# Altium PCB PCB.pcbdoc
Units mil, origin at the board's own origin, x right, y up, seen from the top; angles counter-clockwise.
Board outline 3022 x 1802.5 mil, 4 copper layers (Top Layer, Inner1, Inner2, Bottom Layer); 70 components, 53 nets, 302 pads, 146 vias.
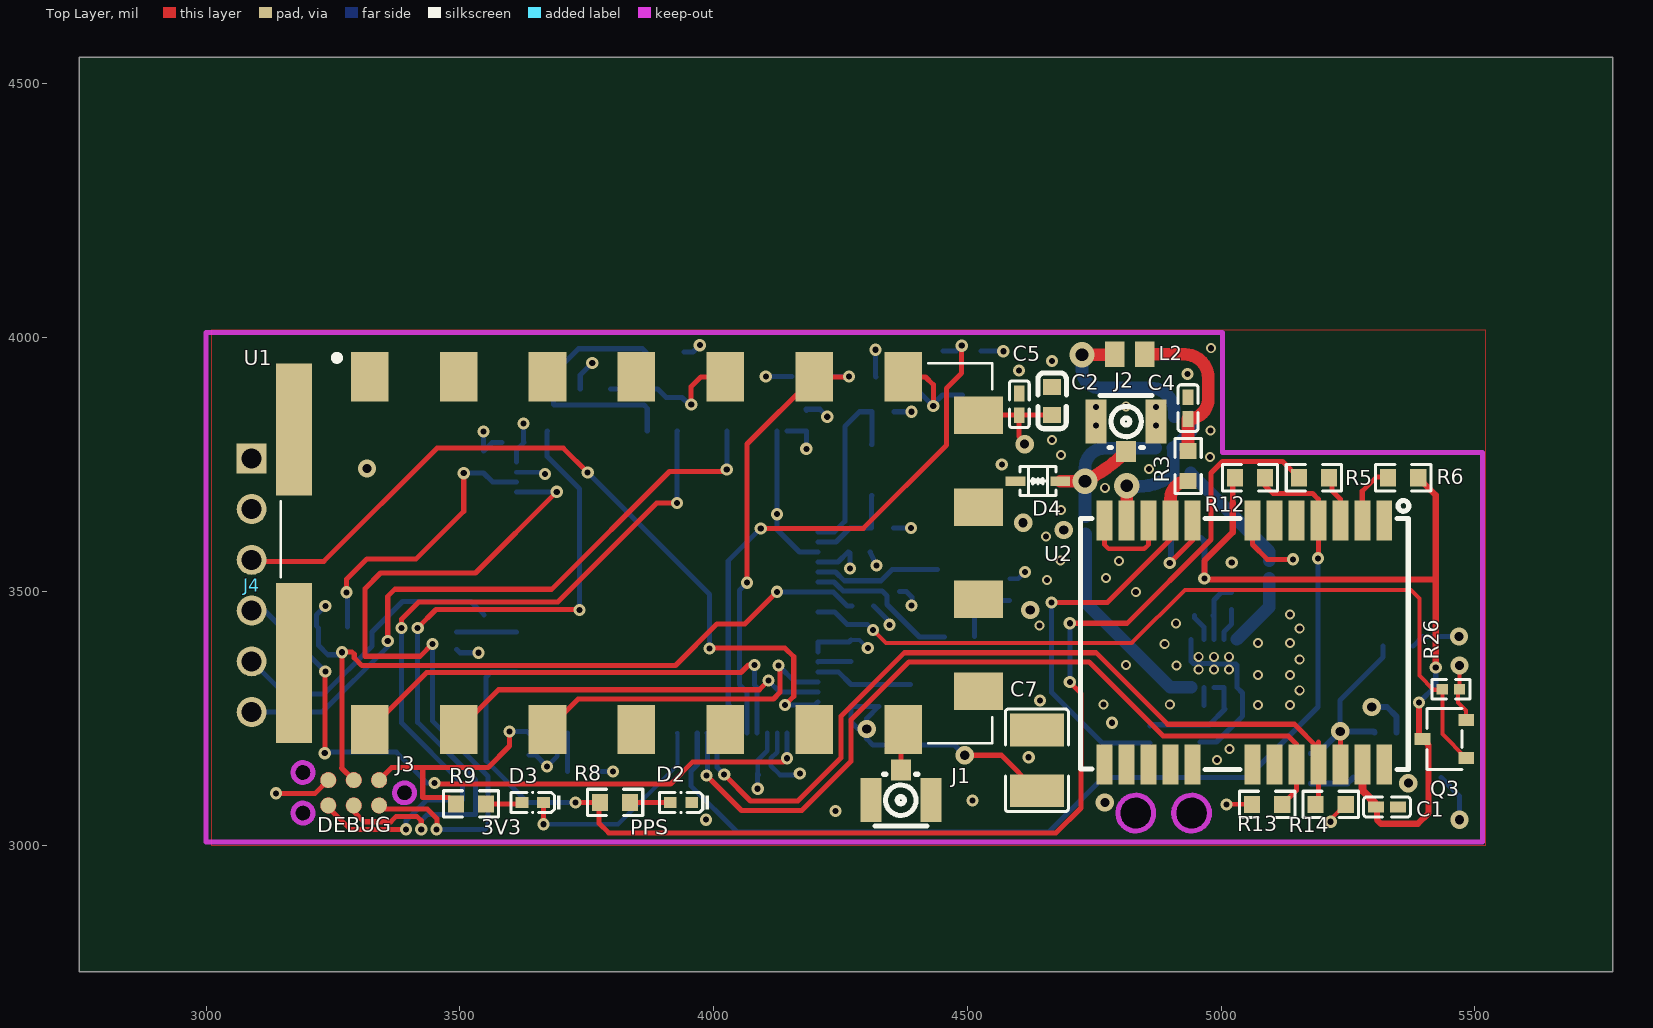
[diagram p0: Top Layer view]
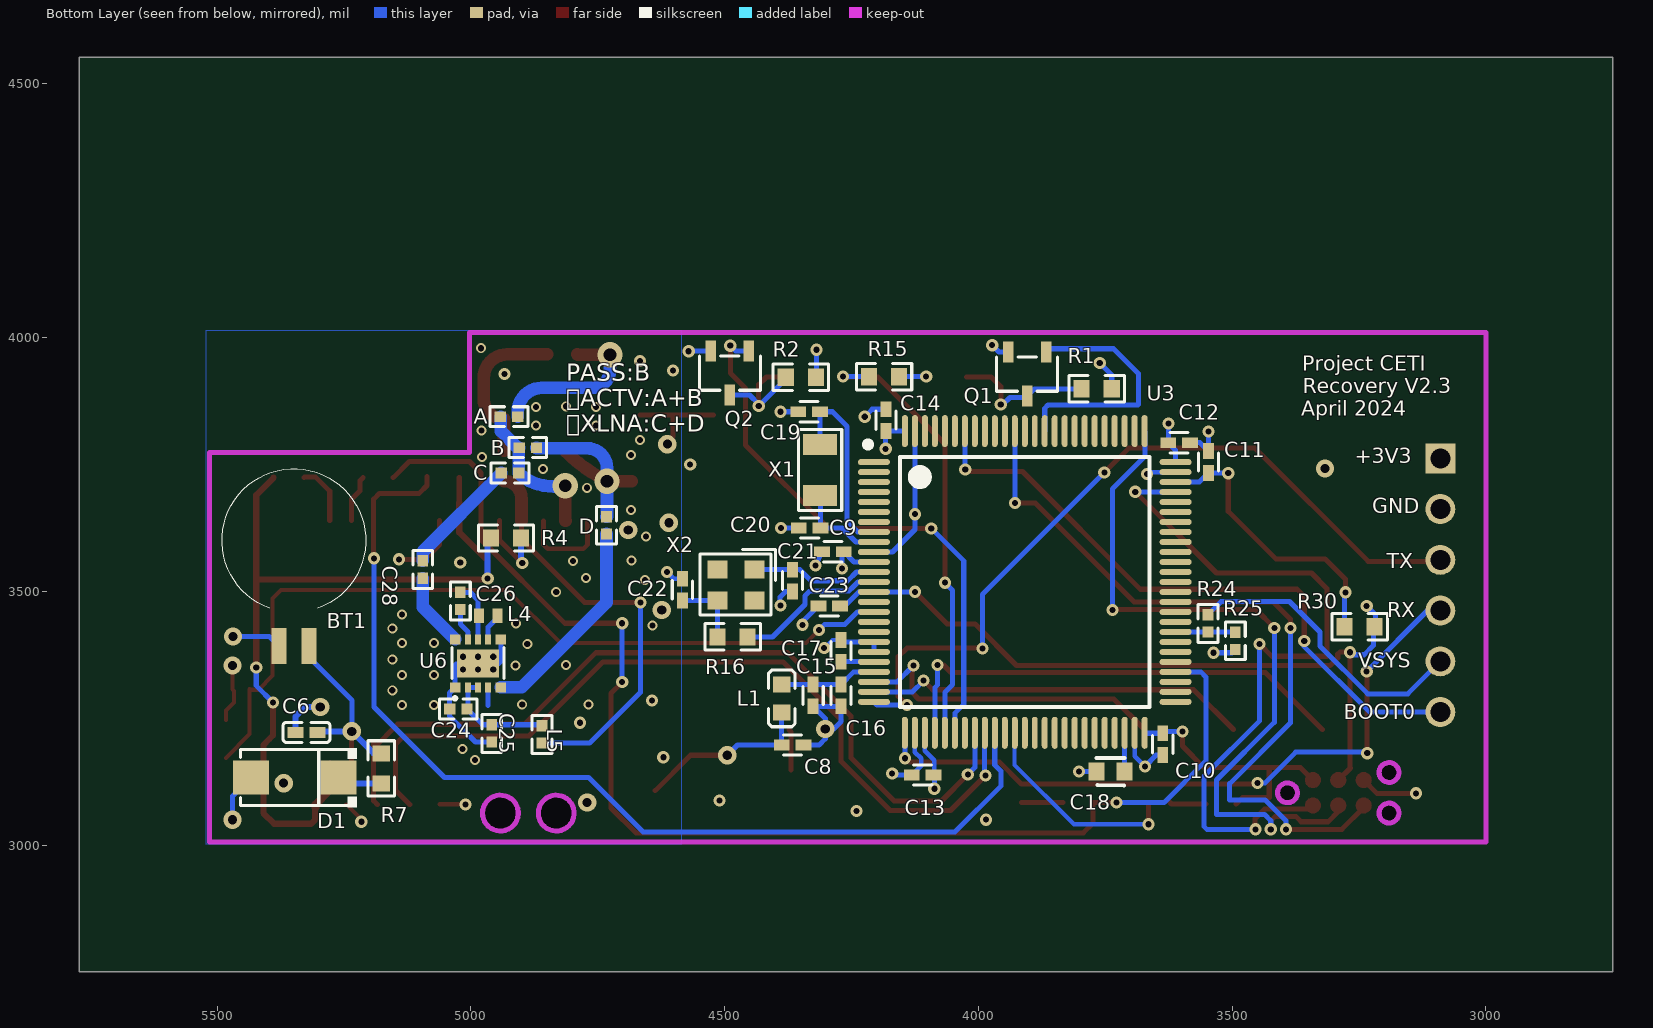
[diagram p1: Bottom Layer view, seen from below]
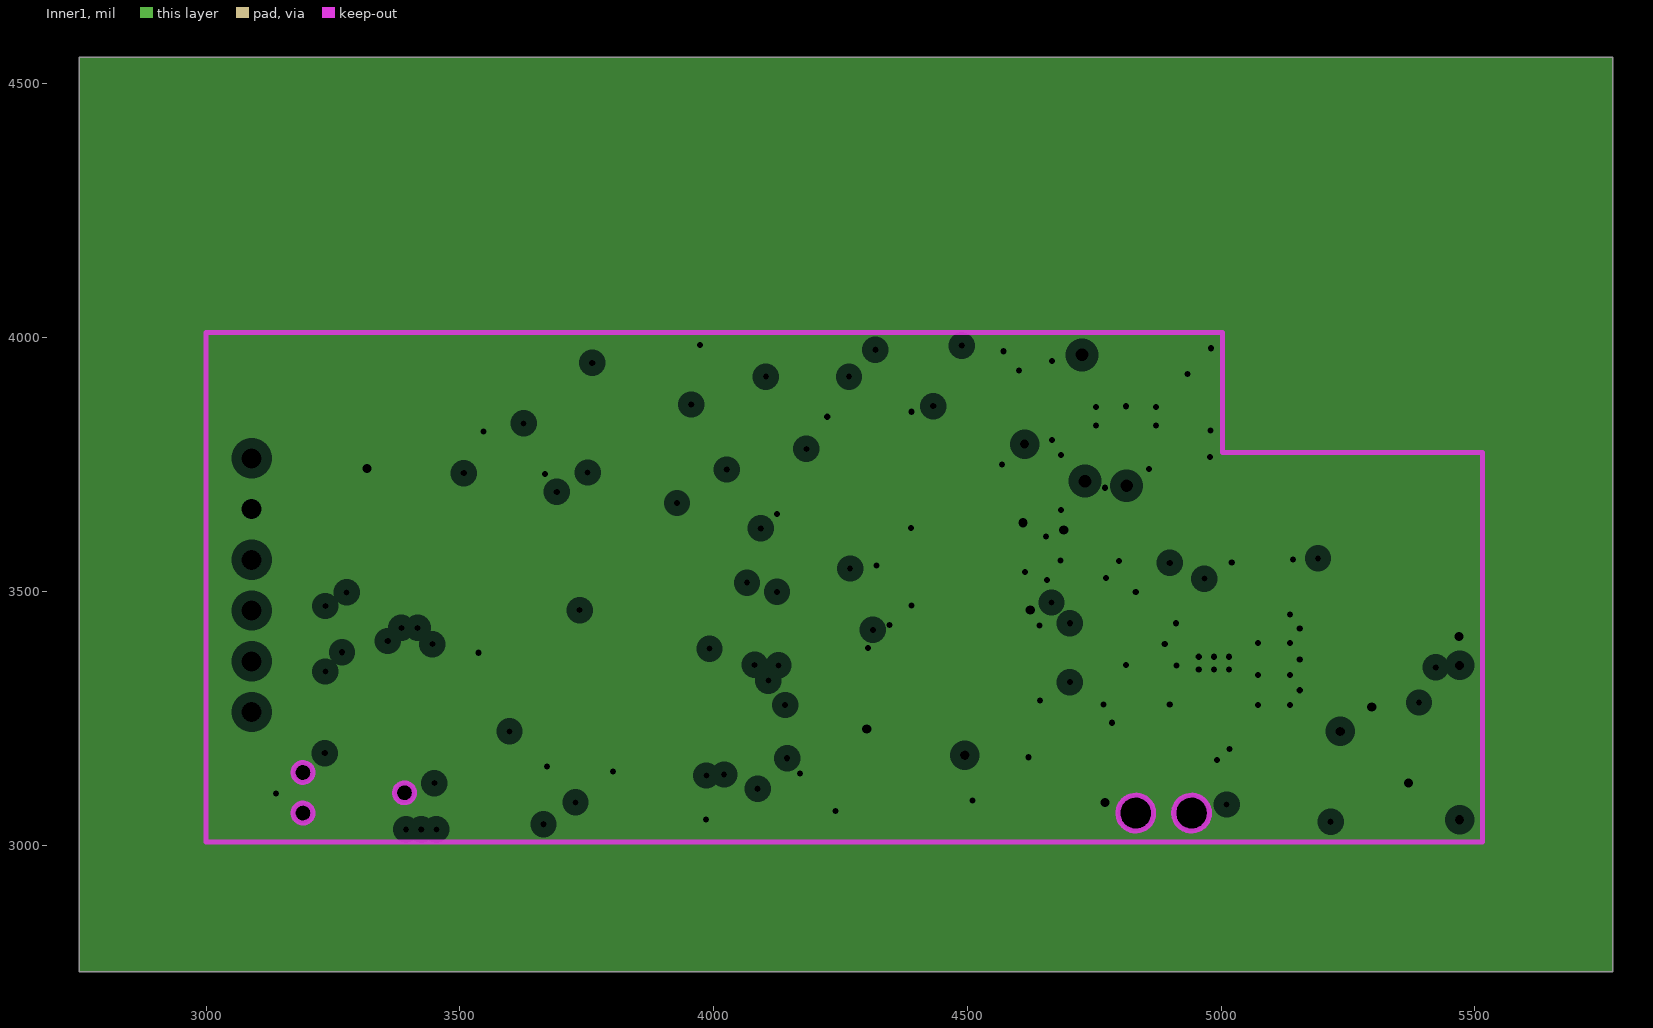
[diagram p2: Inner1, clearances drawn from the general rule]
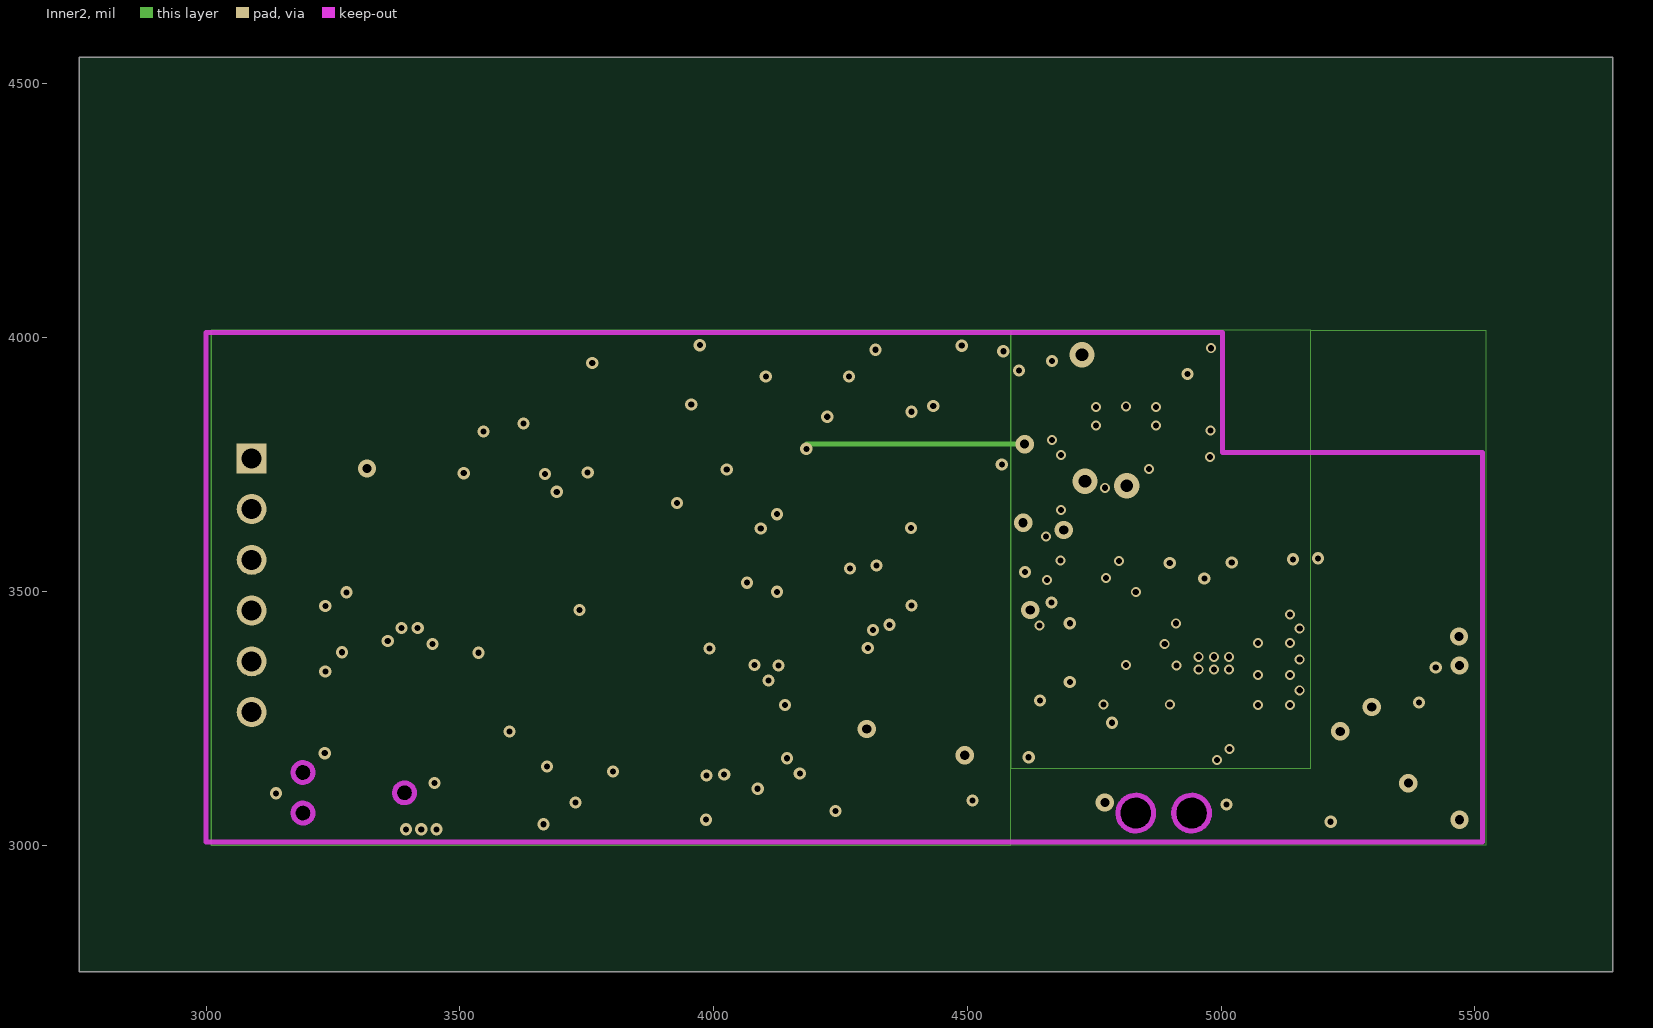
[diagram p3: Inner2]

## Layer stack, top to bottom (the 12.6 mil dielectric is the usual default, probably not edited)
Top Layer: signal copper (thickness not stored)
Dielectric: dielectric 12.6, FR-4, Dk 4.8
Inner1: plane copper (thickness not stored)
Dielectric: dielectric 12.6, FR-4, Dk 4.8
Inner2: signal copper (thickness not stored)
Dielectric: dielectric 12.6, FR-4, Dk 4.8
Bottom Layer: signal copper (thickness not stored)

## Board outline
5772,2750 2750,2750 2750,4552.5 5772,4552.5
cut-out: 4867.3,3063 ccw(c4832,3063) 4796.7,3063 ccw(c4832,3063)
cut-out: 4977.3,3063 ccw(c4942,3063) 4906.7,3063 ccw(c4942,3063)

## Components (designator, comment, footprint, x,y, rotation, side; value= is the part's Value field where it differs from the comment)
A "ERJ2GE0R00X" R0402 4925,3844 r0 bottom
B "ERJ2GE0R00X" R0402 4888,3783 r0 bottom
BT1 "MS621FE-FL11E" MS621FE-FL11E 5349,3392 r180 bottom
C "ERJ2GE0R00X" R0402 4923,3733 r180 bottom
C1 "CC0402KRX5R7BB105" C0402 5327,3075 r180 top
C2 "10uF" C0603 4667,3875 r270 top
C4 "GCM155R71C104KA55J" C0402 4935,3861 r270 top
C5 "100nF" C0402 4602.46,3868.46 r270 top
C6 "1uF" C0402 5324,3222 r180 bottom
C7 "100uF" C1210 4637,3167 r90 top
C8 "100nF" C0402 4366.33,3197.25 r0 bottom
C9 "100nF" C0402 4286.79,3577.79 r180 bottom
C10 "100nF" C0402 3636.79,3198.79 r90 bottom
C11 "100nF" C0402 3546.79,3754.79 r270 bottom
C12 "100nF" C0402 3604.79,3792.79 r0 bottom
C13 "100nF" C0402 4110,3138 r180 bottom
C14 "100nF" C0402 4182.33,3837.25 r270 bottom
C15 "1uF" C0402 4325.79,3294.79 r90 bottom
C16 "10nF" C0402 4270.79,3294.79 r90 bottom
C17 "100nF" C0402 4270.79,3382.79 r270 bottom
C18 "4.7uF" C0603 3739.79,3144.79 r180 bottom
C19 "15pF" C0402 4333.79,3853.79 r180 bottom
C20 "15pF" C0402 4332.79,3624.79 r180 bottom
C21 "6pF" C0402 4366.38,3521.2 r90 bottom
C22 "6pF" C0402 4583.38,3503.2 r270 bottom
C23 "100nF" C0402 4294,3471 r180 bottom
C24 "ERJ2GE0R00X" R0402 5025,3268 r180 bottom
C25 "ERJ2GE0R00X" R0402 4959,3220 r90 bottom
C26 "ERJ2GE0R00X" R0402 5021,3481 r90 bottom
C28 "ERJ2GE0R00X" R0402 5095,3543 r90 bottom
D "ERJ2GE0R00X" R0402 4733,3630 r270 bottom
D1 "SS14L" SMA_L4.4-W2.6-LS5.0-RD 5347,3133 r0 bottom
D2 "16-213/BHC-ZL1M2B6Y/3T" LED0402-RD_BLUE 3936,3084 r180 top
D3 "16-213/SDRC/S530-A3/TR8" LED0402-RD 3643.71,3084 r180 top
D4 "NI" SOD-323_L1.8-W1.3-LS2.5-BI 4639,3717 r0 top
J1 "1909763-1" ANT-SMD_1909763-1 4369,3118 r0 top
J2 "1909763-1" ANT-SMD_1909763-1 4813,3805 r180 top
J3 "TC2030-IDC-NL" TC2030-IDC-NL 3341,3078 r180 top
J4 "CASTELLATION-0.05&quot;-W/-TH" "CASTELLATION-0.05\"-W/-TH" 3000,3912 r0 top
L1 "Ferrite Bead" L0603 4387.81,3288.68 r270 bottom
L2 "CI160808-27NJ" IND_BOURNS_CI160808 4820,3967 r180 top
L4 "LQW15AN9N1J00D_" INDC1006X60N 4966,3452 r0 bottom
L5 "ERJ2GE0R00X" R0402 4860,3218 r90 bottom
Q1 "DMN65D8L-7" SOT-23-3_L3.0-W1.7-P0.95-LS2.9-BR 3904,3928 r90 bottom
Q2 "DMN65D8L-7" SOT-23-3_L3.0-W1.7-P0.95-LS2.9-BR 4490,3930 r90 bottom
Q3 "SSM3J332R,LF" SOT-23F_L2.9-W1.8-P0.95-LS2.4-BR 5440,3209 r0 top
R1 "1k" R0603 3767,3899 r180 bottom
R2 "1k" R0603 4350,3922 r180 bottom
R3 "ESR03EZPJ100" R0603 4935,3747 r90 top
R4 "10k" R0603 4931,3605 r0 bottom
R5 "0 Ohm" R0603 5183,3724 r180 top
R6 "75k" R0603 5359,3724 r0 top
R7 "1k" R0603 5177,3151 r270 bottom
R8 "RC0603JR-07330RL" R0603 3806,3084 r0 top
R9 "RC0603JR-07330RL" R0603 3522,3081 r0 top
R12 "75k" R0603 5057,3724 r180 top
R13 "75k" R0603 5091,3080 r180 top
R14 "75k" R0603 5216,3080 r0 top
R15 "10k" R0603 4186,3923 r180 bottom
R16 "0 Ohm" R0603 4484.38,3410.2 r180 bottom
R24 "10k" R0402 3547.99,3436.68 r90 bottom
R25 "4.22k" R0402 3493.99,3402.49 r90 bottom
R26 "15k" R0402 5453,3307 r0 top
R30 "10k" R0603 3249,3430 r180 bottom
U1 "DRA818V" DORJI_DRA818V 3848,3575 r0 top
U2 "NEO-M9N-00B" GPSM-SMD_24P-L16.0-W12.2-P1.10-BL 5046,3399 r90 top
U3 "STM32U575VGT6" LQFP-100_L14.0-W14.0-P0.50-LS16.0-BL 3908.78,3518.44 r270 bottom
U6 "SKY65943-11" MCM-10_L2.5-W2.5-P0.50-BL-EP 4986,3357.99 r180 bottom
X1 "32.768kHz" OSC-SMD_L3.2-W1.5 4311.8,3738.72 r270 bottom
X2 "16MHz" CRYSTAL-SMD_4P-L2.5-W2.0-BL-A 4477.63,3512.21 r0 bottom

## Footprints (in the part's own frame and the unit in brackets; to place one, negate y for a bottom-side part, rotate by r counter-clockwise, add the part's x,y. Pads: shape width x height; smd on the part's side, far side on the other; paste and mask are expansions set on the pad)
ANT-SMD_1909763-1 [mm]
  rect 1x1.05 smd: 1(0,0.751)
  rect 1.05x2.2 smd: 2(-1.5,-0.751) 2(1.5,-0.751)
  silkscreen extent -1.3,-2.05 1.3,0.55
C0402 [mm]
  rect 0.79x0.54 smd: 1(-0.545,0) 2(0.545,0)
  silkscreen extent -1.17,-0.5 1.17,0.5
C0603 [mm]
  rect 0.8x0.9 smd: 1(-0.7,0) 2(0.7,0)
  silkscreen extent -1.41,-0.71 1.39,0.72
C1210 [mm]
  rect 1.635x2.7 smd: 1(-1.517,0) 2(1.517,0)
  silkscreen extent -2.56,-1.58 2.56,1.58
"CASTELLATION-0.05\"-W/-TH" [mm]
  rect 1.5x1.5 hole 1: 1(2.286,-3.81)
  round 1.5 hole 1: 2(2.286,-6.35) 3(2.286,-8.89) 4(2.286,-11.43) 5(2.286,-13.97) 6(2.286,-16.51)
CRYSTAL-SMD_4P-L2.5-W2.0-BL-A [mm]
  rect 1x0.9 smd: 1(-0.925,-0.775) 2(0.925,-0.775) 3(0.925,0.775) 4(-0.925,0.775)
  silkscreen extent -1.98,-1.78 1.8,1.5
DORJI_DRA818V [mm]
  rect 1.88x2.47 smd: 1(-13.35,8.825) 2(-8.9,8.825) 3(-4.45,8.825) 4(0,8.825) 5(4.45,8.825) 6(8.9,8.825) 7(13.35,8.825) 12(13.35,-8.825) 13(8.9,-8.825) 14(4.45,-8.825) 15(0,-8.825) 16(-4.45,-8.825) 17(-8.9,-8.825) 18(-13.35,-8.825)
  rect 2.47x1.88 smd: 8(17.125,6.9) 9(17.125,2.3) 10(17.125,-2.3) 11(17.125,-6.9)
  rect 1.8x6.6 smd: P2(-17.125,6.2)
  rect 1.8x8 smd: P3(-17.125,-5.5)
  silkscreen extent -17.8,-9.5 17.8,9.93
GPSM-SMD_24P-L16.0-W12.2-P1.10-BL [mm]
  rect 2x0.8 smd: 1(6.1,-7) 2(6.1,-5.9) 3(6.1,-4.8) 4(6.1,-3.7) 5(6.1,-2.6) 6(6.1,-1.5) 7(6.1,-0.4) 8(6.1,2.6) 9(6.1,3.7) 10(6.1,4.8) 11(6.1,5.9) 12(6.1,7) 13(-6.1,7) 14(-6.1,5.9) 15(-6.1,4.8) 16(-6.1,3.7) 17(-6.1,2.6) 18(-6.1,-0.4) 19(-6.1,-1.5) 20(-6.1,-2.6) 21(-6.1,-3.7) 22(-6.1,-4.8) 23(-6.1,-5.9) 24(-6.1,-7)
  silkscreen extent -6.36,-8.23 7.11,8.2
IND_BOURNS_CI160808 [mil]
  rect 39x51 smd: 1(-29.5,0) 2(29.5,0)
INDC1006X60N [mm]
  rect 0.51x0.73 smd: 1(-0.46,0) 2(0.46,0)
L0603 [mm]
  rect 0.8x0.864 smd: 1(-0.7,0) 2(0.7,0)
  silkscreen extent -1.42,-0.65 1.41,0.67
LED0402-RD [mm]
  rect 0.636x0.54 smd: 1(-0.538,0) 2(0.538,0)
  silkscreen extent -1.39,-0.54 1.09,0.54
LED0402-RD_BLUE [mm]
  rect 0.636x0.54 smd: 1(-0.538,0) 2(0.538,0)
  silkscreen extent -1.39,-0.54 1.09,0.54
LQFP-100_L14.0-W14.0-P0.50-LS16.0-BL [mm]
  oval 0.3x1.6 smd: 1(-6,-7.55) 2(-5.5,-7.55) 3(-5,-7.55) 4(-4.5,-7.55) 5(-4,-7.55) 6(-3.5,-7.55) 7(-3,-7.55) 8(-2.5,-7.55) 9(-2,-7.55) 10(-1.5,-7.55) 11(-1,-7.55) 12(-0.5,-7.55) 13(0,-7.55) 14(0.5,-7.55) 15(1,-7.55) 16(1.5,-7.55) 17(2,-7.55) 18(2.5,-7.55) 19(3,-7.55) 20(3.5,-7.55) 21(4,-7.55) 22(4.5,-7.55) 23(5,-7.55) 24(5.5,-7.55) 25(6,-7.55) 51(6,7.55) 52(5.5,7.55) 53(5,7.55) 54(4.5,7.55) 55(4,7.55) 56(3.5,7.55) 57(3,7.55) 58(2.5,7.55) 59(2,7.55) 60(1.5,7.55) 61(1,7.55) 62(0.5,7.55) 63(0,7.55) 64(-0.5,7.55) 65(-1,7.55) 66(-1.5,7.55) 67(-2,7.55) 68(-2.5,7.55) 69(-3,7.55) 70(-3.5,7.55) 71(-4,7.55) 72(-4.5,7.55) 73(-5,7.55) 74(-5.5,7.55) 75(-6,7.55)
  oval 1.6x0.3 smd: 26(7.55,-6) 27(7.55,-5.5) 28(7.55,-5) 29(7.55,-4.5) 30(7.55,-4) 31(7.55,-3.5) 32(7.55,-3) 33(7.55,-2.5) 34(7.55,-2) 35(7.55,-1.5) 36(7.55,-1) 37(7.55,-0.5) 38(7.55,0) 39(7.55,0.5) 40(7.55,1) 41(7.55,1.5) 42(7.55,2) 43(7.55,2.5) 44(7.55,3) 45(7.55,3.5) 46(7.55,4) 47(7.55,4.5) 48(7.55,5) 49(7.55,5.5) 50(7.55,6) 76(-7.55,6) 77(-7.55,5.5) 78(-7.55,5) 79(-7.55,4.5) 80(-7.55,4) 81(-7.55,3.5) 82(-7.55,3) 83(-7.55,2.5) 84(-7.55,2) 85(-7.55,1.5) 86(-7.55,1) 87(-7.55,0.5) 88(-7.55,0) 89(-7.55,-0.5) 90(-7.55,-1) 91(-7.55,-1.5) 92(-7.55,-2) 93(-7.55,-2.5) 94(-7.55,-3) 95(-7.55,-3.5) 96(-7.55,-4) 97(-7.55,-4.5) 98(-7.55,-5) 99(-7.55,-5.5) 100(-7.55,-6)
  silkscreen extent -7.03,-8 6.25,6.25
MCM-10_L2.5-W2.5-P0.50-BL-EP [mm]
  rect 0.52x0.5 smd: 1(-1.144,-1.2) 5(1.144,-1.2) 6(1.144,1.2) 10(-1.144,1.2)
  rect 0.3x0.5 smd: 2(-0.5,-1.2) 3(0,-1.2) 4(0.5,-1.2) 7(0.5,1.2) 8(0,1.2) 9(-0.5,1.2)
  rect 2.1x1.4 smd: 11(0,0)
  silkscreen extent -1.3,-1.83 1.3,0.8
MS621FE-FL11E [mm]
  rect 0.75x1.8 smd: +(0.75,0) -(-0.75,0)
  silkscreen extent -3.59,1.9 3.59,8.88
OSC-SMD_L3.2-W1.5 [mm]
  rect 1.05x1.7 smd: 1(-1.275,0) 2(1.275,0)
  silkscreen extent -2.03,-1.08 2.03,1.08
R0402 [mm]
  rect 0.566x0.54 smd: 1(-0.433,0) 2(0.433,0)
  silkscreen extent -0.94,-0.5 0.94,0.5
R0603 [mil]
  rect 31.75x34.02 smd: 1(-29.66,0) 2(29.66,0)
  silkscreen extent -55,-26 55,26
SMA_L4.4-W2.6-LS5.0-RD [mm]
  rect 1.8x1.7 smd: 1(-2.192,0) 2(2.192,0)
  silkscreen extent -3.11,-1.48 2.73,1.48
SOD-323_L1.8-W1.3-LS2.5-BI [mm]
  rect 0.985x0.49 smd: 1(-1.118,0) 2(1.118,0)
  silkscreen extent -0.9,-0.73 0.9,0.73
SOT-23-3_L3.0-W1.7-P0.95-LS2.9-BR [mil]
  rect 40.85x20.95 smd: 1(43.36,-37.4) 2(43.36,37.4) 3(-43.36,0)
  silkscreen extent -34,-60 34,60
SOT-23F_L2.9-W1.8-P0.95-LS2.4-BR [mm]
  rect 0.785x0.595 smd: 1(1.092,-0.95) 2(1.092,0.95) 3(-1.092,0)
  silkscreen extent -0.88,-1.53 0.88,1.53
TC2030-IDC-NL [mil]
  round 31 smd: 1(0,-50) 2(0,0) 3(50,-50) 4(50,0) 5(100,-50) 6(100,0)
  Top Layer region: -15.5,0 -15.39,1.87 -15.05,3.71 -14.49,5.5 -13.72,7.2 -12.76,8.8 -11.6,10.28 -10.28,11.6 -8.8,12.76 -7.2,13.72 -5.5,14.49 -3.71,15.05 -1.87,15.39 0,15.5 1.87,15.39 3.71,15.05 5.5,14.49 7.2,13.72 8.8,12.76 10.28,11.6 11.6,10.28 12.76,8.8 13.72,7.2 14.49,5.5 15.05,3.71 15.39,1.87 15.5,0 15.39,-1.87 15.05,-3.71 14.49,-5.5 13.72,-7.2 12.76,-8.8 11.6,-10.28 10.28,-11.6 8.8,-12.76 7.2,-13.72 5.5,-14.49 3.71,-15.05 1.87,-15.39 0,-15.5 -1.87,-15.39 -3.71,-15.05 -5.5,-14.49 -7.2,-13.72 -8.8,-12.76 -10.28,-11.6 -11.6,-10.28 -12.76,-8.8 -13.72,-7.2 -14.49,-5.5 -15.05,-3.71 -15.39,-1.87
  Top Layer region: -15.5,-50 -15.39,-48.13 -15.05,-46.29 -14.49,-44.5 -13.72,-42.8 -12.76,-41.19 -11.6,-39.72 -10.28,-38.4 -8.8,-37.24 -7.2,-36.28 -5.5,-35.51 -3.71,-34.95 -1.87,-34.61 0,-34.5 1.87,-34.61 3.71,-34.95 5.5,-35.51 7.2,-36.28 8.8,-37.24 10.28,-38.4 11.6,-39.72 12.76,-41.19 13.72,-42.8 14.49,-44.5 15.05,-46.29 15.39,-48.13 15.5,-50 15.39,-51.87 15.05,-53.71 14.49,-55.5 13.72,-57.2 12.76,-58.8 11.6,-60.28 10.28,-61.6 8.8,-62.76 7.2,-63.72 5.5,-64.49 3.71,-65.05 1.87,-65.39 0,-65.5 -1.87,-65.39 -3.71,-65.05 -5.5,-64.49 -7.2,-63.72 -8.8,-62.76 -10.28,-61.6 -11.6,-60.28 -12.76,-58.8 -13.72,-57.2 -14.49,-55.5 -15.05,-53.71 -15.39,-51.87
  Top Layer region: 34.5,0 34.61,1.87 34.95,3.71 35.51,5.5 36.28,7.2 37.24,8.8 38.4,10.28 39.72,11.6 41.19,12.76 42.8,13.72 44.5,14.49 46.29,15.05 48.13,15.39 50,15.5 51.87,15.39 53.71,15.05 55.5,14.49 57.2,13.72 58.8,12.76 60.28,11.6 61.6,10.28 62.76,8.8 63.72,7.2 64.49,5.5 65.05,3.71 65.39,1.87 65.5,0 65.39,-1.87 65.05,-3.71 64.49,-5.5 63.72,-7.2 62.76,-8.8 61.6,-10.28 60.28,-11.6 58.8,-12.76 57.2,-13.72 55.5,-14.49 53.71,-15.05 51.87,-15.39 50,-15.5 48.13,-15.39 46.29,-15.05 44.5,-14.49 42.8,-13.72 41.19,-12.76 39.72,-11.6 38.4,-10.28 37.24,-8.8 36.28,-7.2 35.51,-5.5 34.95,-3.71 34.61,-1.87
  Top Layer region: 34.5,-50 34.61,-48.13 34.95,-46.29 35.51,-44.5 36.28,-42.8 37.24,-41.19 38.4,-39.72 39.72,-38.4 41.19,-37.24 42.8,-36.28 44.5,-35.51 46.29,-34.95 48.13,-34.61 50,-34.5 51.87,-34.61 53.71,-34.95 55.5,-35.51 57.2,-36.28 58.8,-37.24 60.28,-38.4 61.6,-39.72 62.76,-41.19 63.72,-42.8 64.49,-44.5 65.05,-46.29 65.39,-48.13 65.5,-50 65.39,-51.87 65.05,-53.71 64.49,-55.5 63.72,-57.2 62.76,-58.8 61.6,-60.28 60.28,-61.6 58.8,-62.76 57.2,-63.72 55.5,-64.49 53.71,-65.05 51.87,-65.39 50,-65.5 48.13,-65.39 46.29,-65.05 44.5,-64.49 42.8,-63.72 41.19,-62.76 39.72,-61.6 38.4,-60.28 37.24,-58.8 36.28,-57.2 35.51,-55.5 34.95,-53.71 34.61,-51.87
  Top Layer region: 84.5,0 84.61,1.87 84.95,3.71 85.51,5.5 86.28,7.2 87.24,8.8 88.4,10.28 89.72,11.6 91.19,12.76 92.8,13.72 94.5,14.49 96.29,15.05 98.13,15.39 100,15.5 101.87,15.39 103.71,15.05 105.5,14.49 107.2,13.72 108.8,12.76 110.28,11.6 111.6,10.28 112.76,8.8 113.72,7.2 114.49,5.5 115.05,3.71 115.39,1.87 115.5,0 115.39,-1.87 115.05,-3.71 114.49,-5.5 113.72,-7.2 112.76,-8.8 111.6,-10.28 110.28,-11.6 108.8,-12.76 107.2,-13.72 105.5,-14.49 103.71,-15.05 101.87,-15.39 100,-15.5 98.13,-15.39 96.29,-15.05 94.5,-14.49 92.8,-13.72 91.19,-12.76 89.72,-11.6 88.4,-10.28 87.24,-8.8 86.28,-7.2 85.51,-5.5 84.95,-3.71 84.61,-1.87
  Top Layer region: 84.5,-50 84.61,-48.13 84.95,-46.29 85.51,-44.5 86.28,-42.8 87.24,-41.19 88.4,-39.72 89.72,-38.4 91.19,-37.24 92.8,-36.28 94.5,-35.51 96.29,-34.95 98.13,-34.61 100,-34.5 101.87,-34.61 103.71,-34.95 105.5,-35.51 107.2,-36.28 108.8,-37.24 110.28,-38.4 111.6,-39.72 112.76,-41.19 113.72,-42.8 114.49,-44.5 115.05,-46.29 115.39,-48.13 115.5,-50 115.39,-51.87 115.05,-53.71 114.49,-55.5 113.72,-57.2 112.76,-58.8 111.6,-60.28 110.28,-61.6 108.8,-62.76 107.2,-63.72 105.5,-64.49 103.71,-65.05 101.87,-65.39 100,-65.5 98.13,-65.39 96.29,-65.05 94.5,-64.49 92.8,-63.72 91.19,-62.76 89.72,-61.6 88.4,-60.28 87.24,-58.8 86.28,-57.2 85.51,-55.5 84.95,-53.71 84.61,-51.87
  Multi-Layer board cut-out: -69.5,-25 -67.57,-33.46 -62.16,-40.25 -54.34,-44.01 -45.66,-44.01 -37.84,-40.25 -32.43,-33.46 -30.5,-25 -30.5,-25 -32.43,-16.54 -37.84,-9.75 -45.66,-5.99 -54.34,-5.99 -62.16,-9.75 -67.57,-16.54 -69.5,-25
  Multi-Layer board cut-out: 130.5,15 132.43,6.54 137.84,-0.25 145.66,-4.01 154.34,-4.01 162.16,-0.25 167.57,6.54 169.5,15 169.5,15 167.57,23.46 162.16,30.25 154.34,34.01 145.66,34.01 137.84,30.25 132.43,23.46 130.5,15
  Multi-Layer board cut-out: 130.5,-65 132.43,-73.46 137.84,-80.25 145.66,-84.01 154.34,-84.01 162.16,-80.25 167.57,-73.46 169.5,-65 169.5,-65 167.57,-56.54 162.16,-49.75 154.34,-45.99 145.66,-45.99 137.84,-49.75 132.43,-56.54 130.5,-65

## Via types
v1: diameter 24, hole 12, Top Layer to Bottom Layer, 66 vias
v2: diameter 19.7, hole 12, Top Layer to Bottom Layer, 44 vias
v3: diameter 24.02, hole 12.01, Top Layer to Bottom Layer, 19 vias
v4: diameter 36, hole 18, Top Layer to Bottom Layer, 14 vias
v5: diameter 50, hole 25, Top Layer to Bottom Layer, 3 vias

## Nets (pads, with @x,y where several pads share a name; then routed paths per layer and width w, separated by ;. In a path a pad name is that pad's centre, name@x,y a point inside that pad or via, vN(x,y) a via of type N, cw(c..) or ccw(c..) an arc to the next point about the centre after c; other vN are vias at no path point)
3V3_LED_NEN: D3.1 U3.37 | length 418.9
  Top Layer w10: D3.1 3665,3083.9 v1(3665,3041)
  Bottom Layer w8: v1(3665,3041) 3812,3041 3929,3158 3929,3220.66 U3.37
$1N2852: C22.2 R16.1 X2.3 | length 140
  Bottom Layer w10: R16.1@4514.03,3411.05 X2.3 4514.08,3481.74 C22.2
$2N1313: R6.1 U2.2 | length 121.1
  Top Layer w10: U2.2 5278.28,3697.28 5306,3725 5328.34,3725 R6.1
$2N1327: D1.1 R7.2 | length 88.5
  Bottom Layer w12: R7.2 5249.02,3121.34 D1.1
$2N11296: C4.2 L2.1 R3.2 | length 318.5
  Top Layer w25: L2.1 4928,3967 cw(c4928,3920) 4975,3920 4975,3879.54 cw(c4935,3879.54) C4.2 R3.2
$2N11769: C28.1 U6.10 | length 147.2
  Bottom Layer w25: U6.10 5095,3469.2 C28.1
$2N11796: D.2 U6.5 | length 412.2
  Bottom Layer w25: D.2 4733,3478 4900.25,3310.75 U6.5
$2N14994: D2.2 R8.2 | length 81.2
  Top Layer w10: R8.2@3833.68,3083.75 3914.56,3083.75 D2.2
$2N19088: L4.1 U6.7 | length 54.4
  Bottom Layer w10: L4.1 4947.89,3447.67 4966.31,3429.25 U6.7
$2N19111: C26.2 L4.2 U6.8 | length 120.6
  Bottom Layer w10: U6.8 4986,3450.11 L4.2 4986,3453.89 4986,3483 5001.04,3498.04 C26.2
$3N108: D3.2 R9.2 | length 72.1
  Top Layer w10: R9.2 3619.52,3081 D3.2
+3V3: C2.2 C5.2 C7.1 C8.2 C9.2 C10.2 C11.2 C12.2 C13.2 C14.2 D1.2 J3.1 J4.1 L1.2 Q3.2 R1.2 R2.2 R9.1 R13.2 R14.2 R15.2 R26.2 R30.1 U1.8 U3.11 U3.28 U3.50 U3.73 U3.75 U3.100 | length 3020
  Top Layer w8: v1(5216,3046) 5216,3050.34 R14.2 ; v4(5470,3354) R26.2 5467,3303.96 5467,3281 5483.01,3264.99 Q3.2
  Top Layer w9: v1(5011,3080) R13.2
  Top Layer w10: v1(3277,3498) 3277,3524 3317,3564 3414,3564 3507.79,3657.79 v3(3507.79,3732.79) ; J3.1 3365.5,3152.5 3427,3152.5 ; R9.1 3479.34,3094 3427,3094 3427,3152.5 ; v3(3598,3224) 3598,3195 3555.5,3152.5 3427,3152.5 ; v4(4495,3177) 4567.26,3177 C7.1 ; v4(4613,3790) 4613,3794 4602,3805 4602,3846.54 C5.2 4522.56,3847 4523,3847.44 C2.2
  Inner2 w10: v3(4182.79,3780.79) 4182.79,3790 v4(4613,3790)
  Bottom Layer w9: C13.2@4087,3140.46 4087,3167 4105.63,3185.63 U3.28
  Bottom Layer w10: v1@3278,3496 3278.66,3495.34 R30.1 ; v3(3507.79,3732.79) 3546.24,3732.79 C11.2 3564.83,3715.29 U3.73 ; v3(3598,3224) 3633.04,3224 C10.2 U3.50@3672.56,3220.25 ; U3.75 3611.54,3778.09 C12.2 3625.79,3793.25 v3(3625.79,3830.79) ; R1.2 3737.34,3926.34 v1(3761,3950) ; v3(4087,3111) C13.2@4087,3139.54 ; C13.2@4087,3140.46 C13.2@4087,3139.54 ; C13.2 C13.2@4087,3139.54 ; v1(4103,3923) R15.2@4154.7,3923 ; U3.100@4145,3815.79 C14.2 4182.79,3815.33 v3(4182.79,3780.79) ; U3.11 4245.34,3557.81 C9.2 ; C9.2@4266.33,3577.79 4268.79,3575.33 v3@4268.79,3540.79 ; v1(4319,3976) 4319,3923.34 R2.2 ; L1.2 C8.2 ; C8.2@4389.75,3197.25 C8.2 ; v4(4495,3177) 4474.75,3197.25 C8.2 ; D1.2 5470,3096.32 v4(5470,3050)
  other v3: 4269,3545
+3V3A: C15.2 C16.2 L1.1 U3.22 | length 192.1
  Bottom Layer w10: U3.22 4245.77,3341.27 C16.2 C15.2 L1.1
ANT: J1.1 U1.12 | length 81.9
  Top Layer w10: J1.1 4368.99,3222.97 U1.12
BOOT0: J4.6 U3.94 | length 1268
  Top Layer w10: v1(3358,3402) 3358,3490 3372,3504 3681,3504 3913,3736 4022,3736 v1(4026,3740)
  Bottom Layer w10: J4.6 3229,3262 3358,3391 v1(3358,3402) ; v1(4026,3740) 4026.89,3740.89 U3.94
EXT_RX: J4.4 U3.26 | length 1365.4
  Top Layer w10: v1(3234,3181) 3234,3341 v1(3235,3342) ; v1(3450,3122) 3452,3120 3915,3120 3959,3164 4138,3164 v1(4145,3171)
  Bottom Layer w10: J4.4 3115,3462 v1(3235,3342) ; v1(3234,3181) 3236,3183 3374.86,3183 3435.86,3122 v1(3450,3122) ; v1(4145,3171) U3.26
EXT_TX: J4.3 U3.25 | length 1563.6
  Top Layer w10: J4.3 3093,3559 3232,3559 3455,3782 3704,3782 v1(3752,3734) ; v1(3992,3387) 3993,3388 4141,3388 4158,3371 4158,3293 v1(4141,3276)
  Bottom Layer w10: v1@3753,3733 3992,3494 v1(3992,3387) ; v1(4141,3276) 4199.8,3276 U3.25
EXTINT: R12.1 U2.4 U3.35 | length 2025.7
  Top Layer w10: R12.1@5086.66,3726 5086.66,3708.34 5102,3693 5180,3693 5191.67,3681.33 U2.4@5191.67,3641.16 ; v1(5191,3565) 5191.67,3565.67 U2.4
  Bottom Layer w10: U3.35 3967.84,3157.84 3956,3146 3956,3116 4046,3026 4661,3026 4768,3133 5052,3133 5191,3272 v1(5191,3565)
GND: BT1.- C1.1 C2.1 C4.1 C5.1 C6.1 C7.2 C8.1 C9.1 C10.1 C11.1 C12.1 C13.1 C14.1 C15.1 C16.1 C17.1 C18.1 C19.1 C20.1 C21.1 C22.1 C23.1 C24.1 C25.1 C26.1 D2.1 D4.1 J1.2 J2.2 J3.5 J4.2 Q1.2 Q2.2 R25.1 U1.9 U1.10 U2.7 U2.10 U2.12 U2.13 U2.24 U3.10 U3.19 U3.20 U3.27 U3.49 U3.74 U3.99 U6.1 U6.4 U6.6 U6.9 U6.11 | length 2573.8
  Top Layer w9: U2.12 4770.41,3591.9 4778.31,3584 4849,3584 4857.02,3592.02 U2.10
  Top Layer w10: v1(3138,3102) 3215,3102 J3.5 ; U2.7 5061.75,3592.25 5091,3563 v1(5142,3563)
  Bottom Layer w8: C17.1 4287.75,3404.25 v3(4304,3388)
  Bottom Layer w9: U3.74 3664.02,3734.98 v1(3668,3731) ; v3(3672,3155) 3692.24,3175.24 U3.49 ; U3.27 4125.32,3183.2 4113,3170.89 4113,3156.46 C13.1 ; C22.1 4600.66,3524.66 v3(4614,3538)
  Bottom Layer w10: R25.1 3500.44,3379 v3(3537,3379) ; v3(3546.79,3814.79) C11.1 3563.32,3792.79 C12.1 ; C10.1 3649.67,3177.33 v3(3672,3155) ; C18.1 v3(3801.88,3144.79) ; Q1.2 3959.36,3971.36 v1(3973,3985) ; U3.99 4125.32,3652.32 v3(4125,3652) 4125,3622 4169.5,3577.5 U3.10 ; C13.1 4167,3138 v3(4170,3141) ; C14.1 4209.29,3858.71 v3(4224,3844) ; C14.1@4183.33,3856.51 C14.1@4183.41,3856.59 ; U3.20 U3.19 4266.86,3400.33 C17.1 ; C16.1 C15.1 4301.79,3249.33 4301.79,3209.25 4313.79,3197.25 C8.1 ; C16.1@4270.79,3275.11 4270.79,3243.22 4285.21,3228.79 v4(4301.79,3228.79) ; C9.1 4308.79,3577.25 v3(4321,3551) ; C23.1 4347,3439.46 v1(4347,3434) ; C20.1 v3(4388.79,3624.79) ; C19.1 v3(4389.79,3853.79) ; C21.1 4379.84,3499.74 4390.79,3488.79 4390.79,3472.79 v3(4389.79,3471.79) ; Q2.2 4570.64,3973.36 v1(4571,3973) ; U6.6 4940.96,3362.04 4945,3358 U6.11 4987,3357 5029,3357 5031.04,3354.96 U6.1 5042.04,3299.75 C24.1 5042.04,3254.04 4991,3203 C25.1 ; 4966.31,3275 U6.4 ; U6.9 5005.68,3420.08 5021,3435.4 C26.1 ; BT1.- 5397.53,3411 v4(5469,3411)
  Bottom Layer w12: v4(5297,3272) 5327,3272 5345.46,3253.54 C6.1
  other v1: 3985,3050 4240,3067 4510,3088 4621,3173 4785,3241 4643,3285 5021,3556.55 4568,3750 4934,3928 4602,3935 4667,3954
  other v2: 4992,3168 5017,3189 5073,3276 5136,3276 4768,3277 4899,3277 5155,3305 5073,3335.46 5136,3335 4956,3346 4986,3346 5016,3346 4912,3354 4813,3355 5155,3366 4956,3371 4986,3371 5016,3371 4889,3396 5073,3398 5136,3398 5155,3427 4642,3433 4911,3437 5136,3454 4832,3499 4657,3522 4773,3526 4799,3560 4684,3561 4655,3608 4685,3660 4771,3704 4858,3741 4978,3765 4685,3768.82 4666.99,3798.03 4979,3817 4754,3827 4872,3827 4754,3863 4872,3863 4813.01,3864.59 4980,3979
  other v4: 4771,3084 5369,3122 4624,3463 4690,3621 4610,3635 3317,3742
GPS_ANT: B.1 D4.2 D.1 J2.1 | length 407.6
  Top Layer w25: D4.2 v5(4732,3717) ccw(c4592.24,3996.18) J2.1
  Bottom Layer w25: D.1 cw(c4733,3648.04) 4732,3648.04 v5(4732,3717) 4732,3743 cw(c4771,3743) 4771,3782 4869.96,3782 ccw(c4869.96,3783) B.1
GPS_NEN: Q3.1 R26.1 U3.16 | length 1629
  Top Layer w8: v1(4314,3424) 4340,3398 4824,3398 4929,3503 5374,3503 5391,3486 5391,3334 5419,3306 5434.96,3306 R26.1 5435.96,3218.65 Q3.1
  Bottom Layer w10: U3.16 4238.62,3459.38 4263,3435 4303,3435 v1(4314,3424) v1@4317,3427
GPS_RX: R14.1 U2.21 U3.33 | length 1653.1
  Top Layer w10: v1(4021,3139) 4073,3087 4166,3087 4251,3172 4251,3254 4376,3379 4754,3379 4895,3238 5144.68,3238 U2.21@5191.67,3191.01 ; R14.1@5184.5,3080 5191.67,3087.16 U2.21 U2.21@5191.67,3191.01 ; 5191.67,3203.18 U2.21@5191.67,3191.01
  Bottom Layer w10: U3.33 4007.21,3152.7 v1@4020.91,3139
GPS_TX: R13.1 U2.20 U3.34 | length 1643.1
  Top Layer w10: v1(3986,3137) 4055,3068 4174,3068 4271,3165 4271,3247 4385,3361 4740,3361 4886,3215 5132.37,3215 5148.36,3199.01 U2.20 5148.36,3107.7 R13.1
  Bottom Layer w10: v1(3986,3137) 3988,3139 3988,3220.72 U3.34
GPS_VIN: C1.2 Q3.3 R4.2 R6.2 R12.2 U2.23 | length 1692.2
  Top Layer w10: 5023,3676 R12.2@5023,3724
  Top Layer w12: 5023,3675 5023,3616 4967,3560 v1(4967,3525) 4969,3523 5423,3523 ; C1.2@5306,3074 5307,3073 5307,3050 5315,3042 5388,3042 5409,3063 5409,3197 Q3.3 5390,3216 v1(5390,3281) ; R6.2 5423,3689.66 5423,3523 ; v1(5423,3350) 5423,3523
  Top Layer w15.5: U2.23 5279,3158.12 5279,3107 5306,3080 C1.2@5306,3074
  Bottom Layer w10: v1(5390,3281) 5423,3314 v1(5423,3350)
  Bottom Layer w12: R4.2 4967,3598.66 v1(4967,3525)
MIC_IN: U1.18 U3.29 | length 947.2
  Top Layer w10: U1.18 3434.85,3340 4054,3340 4069,3355 v1(4081,3355)
  Bottom Layer w10: v1@4080.95,3354.95 4080.95,3315.05 4086,3310 U3.29@4086,3221.25
NRST: C23.2 J3.3 R30.2 U3.14 | length 1498.2
  Top Layer w10: v1(3235,3471) v1@3237,3471 ; J3.3 3267,3152 3268,3153 v1(3268,3380) 3288,3380 3292,3376 3292,3369 3307,3354 3925,3354 4007,3436 4062,3436 v1(4125,3499)
  Bottom Layer w10: v1(3235,3471) 3217.34,3453.34 3217.34,3432 R30.2 3222,3427.34 3222,3393 3240,3375 3263,3375 v1(3268,3380) ; v1(4125,3499) 4205.77,3499 U3.14 4235.87,3498.75 4263.62,3471 C23.2
OSC16_IN: C21.2 U3.12 X2.1 | length 251.6
  Bottom Layer w10: U3.12 4240.46,3538.12 4257.79,3520.79 4329.79,3520.79 4351.72,3542.73 C21.2@4366.46,3542.73 ; C21.2 C21.2@4366.46,3542.73 ; X2.1 C21.2@4366.46,3542.73
OSC16_OUT: R16.2 U3.13 | length 303.9
  Bottom Layer w10: U3.13 4237.53,3518.44 4248.36,3507.61 ; 4248.74,3507.61 4248.36,3507.61 ; R16.2 4405.82,3410.2 4342.01,3474 4342.01,3491 4332.01,3501 4254.97,3501 4248.36,3507.61
OSC32_IN: C19.2 U3.8 X1.1 | length 379.1
  Bottom Layer w10: U3.8 4237.86,3616.87 4258.79,3637.79 4258.79,3824.79 4287.79,3853.79 C19.2 4312.33,3789.44 X1.1
OSC32_OUT: C20.2 U3.9 X1.2 | length 180.7
  Bottom Layer w10: U3.9 4241.17,3597.18 4268.79,3624.79 C20.2 4311.33,3688.05 X1.2
PERIPH: A.1 L2.2 | length 333.3
  Top Layer w25: v5(4726,3966) 4789.5,3966 L2.2
  Bottom Layer w25: v5(4726,3966) 4726,3936 ccw(c4761,3936) 4761,3901 4860,3901 cw(c4860,3853.04) 4907.96,3853.04 A.1
PPS: R5.1 U2.3 | length 94.1
  Top Layer w10: R5.1 5218.66,3718 5218.66,3697.99 5234.98,3681.67 U2.3
PPS_OUT: R5.2 R8.1 U3.54 | length 2550.5
  Top Layer w10: v1(3728,3084) 3774.11,3084 3774.36,3083.75 3774.36,3043 3793.36,3024 4675,3024 4724,3073 4724,3299 v1(4702,3321) ; v1(4702,3437) 4815,3437 4980,3602 4980,3733 5003,3756 5121.34,3756 R5.2
  Bottom Layer w10: U3.54 3562,3341.27 3552,3331.27 3552,3166 3634,3084 v1(3728,3084) ; v1(4702,3321) v1(4702,3437)
PTT: Q1.3 R1.1 U1.5 | length 283.2
  Top Layer w10: v1(3956,3868) 3956,3903.44 3975,3922.44 U1.5
  Bottom Layer w10: R1.1 3889.64,3899 Q1.3 ; Q1.3@3903.64,3885 3906.64,3882 3938,3882 3952,3868 v1(3956,3868)
PTT_IN: Q1.1 U3.86 | length 498
  Bottom Layer w10: Q1.1 3859.96,3978 3734,3978 3685,3929 3685,3868 3686,3867 3863,3867 3869.41,3860.59 U3.86
PWR_LVL: Q2.3 R2.1 U1.7 | length 255
  Top Layer w10: U1.7 4417.56,3922.44 4433,3907 v1(4433,3865)
  Bottom Layer w10: R2.1 4379.66,3918.34 v1(4433,3865) 4433,3868.64 4451,3886.64 Q2.3
PWR_LVL_IN: Q2.1 U3.31 | length 1119.8
  Top Layer w10: v1(4093,3624) 4295,3624 4459,3788 4459,3900 4489,3930 v1(4489,3984)
  Bottom Layer w10: U3.31 4046.58,3259.7 4029,3277.27 4029,3560 v1(4093,3624) ; Q2.1 4478.36,3973.36 v1(4489,3984)
RESET_N: R4.1 U2.8 | length 151.6
  Top Layer w10: v1(4899,3556) 4943.64,3600.64 U2.8
  Bottom Layer w12: v1(4899,3556) 4901.34,3558.34 R4.1
RF_IN: A.2 B.2 C.2 U2.11 | length 295.6
  Top Layer w25: U2.11 ccw(c4813.04,3639.84) 4814,3639.84 v5(4814,3708)
  Bottom Layer w25: v5(4814,3708) ccw(c4833.95,3836.42) 4868,3711 ccw(c4845.65,3793.31) C.2 4905.96,3782.08 ccw(c4905.04,3782.08) 4905.36,3782.94 4908.19,3782.82 4941.04,3815.67 A.2@4941.04,3844
SLEEP: R15.1 U1.6 U3.30 | length 887
  Top Layer w10: v1(4066,3517) 4066,3790.05 U1.6 4266.44,3922.44 v1(4267,3923)
  Bottom Layer w10: v1(4066,3517) 4051,3502 4051,3316 4066,3301 4066,3221.46 U3.30 ; R15.1@4217.5,3923 v1(4267,3923)
SWCLK: J3.4 U3.76 | length 1425.7
  Top Layer w10: J3.4 3291,3066 3311,3046 3364,3046 3374,3056 3416,3056 3424,3048 v1@3424,3041 ; v1(3417,3428) 3453,3464 3735,3464 v1(3736,3463)
  Bottom Layer w10: v1(3417,3428) 3417,3242 3531,3128 3531,3060 3436,3060 3424,3048 v1(3424,3031) ; U3.76 3672,3815.12 3672,3766 3736,3702 v1(3736,3463)
SWDIO: J3.2 U3.72 | length 1466.5
  Top Layer w10: J3.2 3348,3071 3436,3071 3455,3052 v1@3455,3031 ; v1(3446,3396) 3422,3372 3313,3372 3313,3505 3344,3536 3531,3536 v1(3691,3696)
  Bottom Layer w10: v1(3446,3396) 3446,3245 3556,3135 3556,3037 3550,3031 v1@3455,3031 ; U3.72 3690.61,3695.61 v1(3691,3696)
  other v1: 3454,3031
SWO: J3.6 U3.89 | length 1505.2
  Top Layer w10: J3.6 3241,3074 3284,3031 v1(3394,3031) ; v1(3385,3428) 3385,3445 3419,3479 3693,3479 3888,3674 v1(3928,3674)
  Bottom Layer w10: v1(3385,3428) 3385,3241 3505,3121 3505,3089 3435,3089 3394,3048 v1(3394,3031) ; v1(3928,3674) 3928,3815.22 U3.89
V_BCKP: BT1.+ C6.2 R7.1 U2.22 | length 413.3
  Top Layer w10: U2.22 v4(5235,3224)
  Bottom Layer w10: v4(5235,3224) 5234,3225 5234,3285 5319.47,3370.47 BT1.+
  Bottom Layer w12: R7.1 5191.66,3180.66 v4(5235,3224) 5300.54,3224 C6.2
VCAP: C18.2 U3.48 | length 76.5
  Bottom Layer w10: U3.48 3712.23,3220.9 C18.2
VCC_RF: L5.1 R3.1 U2.9 | length 833
  Top Layer w10: v1(4666,3478) 4776,3478 4900.33,3602.33 U2.9
  Top Layer w25: U2.9 4900.33,3682.67 cw(c4935,3682.67) R3.1
  Bottom Layer w10: v1(4666,3478) 4666,3301 4766,3201 L5.1
VEN: C24.2 C25.2 L5.2 U6.2 U6.3 | length 226.3
  Bottom Layer w10: L5.2 4862,3237.04 C25.2 4977,3237.04 C24.2 5005.68,3268 U6.2 U6.3
VHF_RX: U1.16 U3.23 | length 634.8
  Top Layer w10: U1.16 3733.24,3288 4118,3288 4131,3301 4131,3351 v1(4128,3354)
  Bottom Layer w10: v1(4128,3354) 4161,3321 4205.43,3321 U3.23
VHF_TX: U1.17 U3.24 | length 757.7
  Top Layer w10: U1.17 3576.06,3306.02 4090.02,3306.02 v1(4108,3324)
  Bottom Layer w10: v1(4108,3324) 4130.3,3301.7 4205.82,3301.7 U3.24
VREF+: C17.2 U3.21 | length 64.9
  Bottom Layer w10: U3.21 4206.39,3361.33 C17.2
VSYS: J4.5 R24.2 | length 587.2
  Bottom Layer w10: J4.5 3154,3298 3233,3298 3327,3392 3327,3420 3387,3480 3521.71,3480 R24.2
VSYS_IN: R24.1 R25.2 U3.58 | length 118.2
  Bottom Layer w10: R25.2 3547.58,3419.53 3547.99,3419.94 R24.1 3611.17,3419.64 U3.58
XLNA: C28.2 C.1 | length 237.1
  Bottom Layer w25: C.1 5095,3578.04 C28.2
pads on no net: U1.1 U1.2 U1.3 U1.4 U1.11 U1.13 U1.14 U1.15 U1.P2 U1.P3 U2.1 U2.5 U2.6 U2.14 U2.15 U2.16 U2.17 U2.18 U2.19 U3.1 U3.2 U3.3 U3.4 U3.5 U3.6 U3.7 U3.15 U3.17 U3.18 U3.32 U3.36 U3.38 U3.39 U3.40 U3.41 U3.42 U3.43 U3.44 U3.45 U3.46 U3.47 U3.51 U3.52 U3.53 U3.55 U3.56 U3.57 U3.59 U3.60 U3.61 U3.62 U3.63 U3.64 U3.65 U3.66 U3.67 U3.68 U3.69 U3.70 U3.71 U3.77 U3.78 U3.79 U3.80 U3.81 U3.82 U3.83 U3.84 U3.85 U3.87 U3.88 U3.90 U3.91 U3.92 U3.93 U3.95 U3.96 U3.97 U3.98 X2.2 X2.4

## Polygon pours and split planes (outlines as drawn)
GND on Top Layer (solid, remove dead copper, pour order 0): 3010,3000 5522,3000 5522,4014 3010,4014
GND on Bottom Layer (solid, remove dead copper, pour order 4): 4586,3002 5522,3002 5522,4014 4586,4014
+3V3 on Inner2 (solid, remove dead copper): 3010,3000 4585.98,3000 4585.98,4014 3010,4014
GND on Inner2 (solid, remove dead copper): 4585.96,3151 5177,3151 5177,4014 4585.96,4014
+3V3 on Inner2 (solid, remove dead copper): 3010,4014 4585.98,4014 4585.98,3150.99 5177,3150.99 5177,4014 5522,4014 5522,3000 3010,3000
GND on Inner1 (split plane): 3010.1,3016.1 3010.1,3999.84 4473.58,3999.84 ccw(c4477.16,3989) 4466.9,3984 ccw(c4477.95,3972.95) 4489,3961.9 ccw(c4500.05,3972.95) 4511.1,3984 ccw(c4500.84,3989) 4504.42,3999.84 4716.67,3999.84 ccw(c4777.74,3926.6) 4690.9,3966 ccw(c4708.45,3948.45) 4726,3930.9 ccw(c4743.55,3948.45) 4761.1,3966 ccw(c4674.26,3926.6) 4735.33,3999.84 4992.87,3999.84 4992.87,3773.72 ccw(c4997.92,3768.66) 5002.97,3763.61 5504.68,3763.62 5504.68,3016.1 3470.32,3016.1 ccw(c3461.27,3028.18) 3476.1,3031 ccw(c3465.05,3042.05) 3454,3053.1 ccw(c3450.9,3038.93) 3439,3047.23 ccw(c3427.1,3038.93) 3424,3053.1 ccw(c3420.9,3038.93) 3409,3047.23 ccw(c3397.1,3038.93) 3394,3053.1 ccw(c3382.95,3042.05) 3371.9,3031 ccw(c3386.73,3028.18) 3377.68,3016.1
GND on Inner1 (split plane): 3085,3662 3085,3701.73 3095,3701.73 3095,3662
GND on Inner1 (split plane): 3095,3662 3095,3622.27 3085,3622.27 3085,3662
GND on Inner1 (split plane): 3090,3667 3129.73,3667 3129.73,3657 3090,3657
GND on Inner1 (split plane): 3050.27,3667 3090,3667 3090,3657 3050.27,3657

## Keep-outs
Board Outline Layer:
  lines w10: 5514.78,3773.72 5002.97,3773.72 5002.97,4009.94 3000,4009.94 3000,3006 5514.78,3006 5514.78,3773.72 ; 5514.78,3773.72 5514.78,3773.72
Multi-Layer:
  circle w10: c4832,3063 r35.3
  circle w10: c4942,3063 r35.3
  circle w10: c3391,3103 r19.5
  circle w10: c3191,3063 r19.5
  circle w10: c3191,3143 r19.5

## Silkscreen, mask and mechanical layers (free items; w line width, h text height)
Top Silkscreen Layer:
  text "DEBUG" at 3218.94,3024.99 h29.2
  text "3V3" at 3542.51,3019.99 h29.2
  text "PPS" at 3835.51,3019.99 h29.2
Bottom Silkscreen Layer:
  text "Project CETI" at 3361.96,3934.99 h29.2
  text "Recovery V2.3" at 3360.68,3889.99 h29.2
  text "April 2024" at 3363.53,3845.99 h29.2
  text "PASS:B /  ACTV:A+B /  XLNA:C+D" at 4812.47,3813.99 h33.54
  text "+3V3" at 3258.22,3751.99 h29.2
  text "GND" at 3224.51,3653.99 h29.2
  text "TX" at 3195.79,3544.99 h29.2
  text "RX" at 3194.79,3448.99 h29.2
  text "VSYS" at 3251.22,3348.99 h29.2
  text "BOOT0" at 3279.94,3247.99 h29.2
Mechanical Layer:
  circle w1: c4832,3063 r35.3
  circle w1: c4942,3063 r35.3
